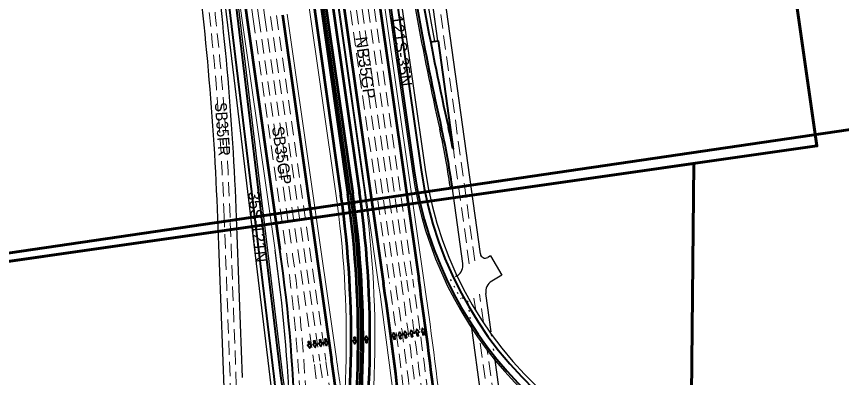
# Model space of a CAD drawing. Extents: x 2329387 to 2347382, y 6951580 to 6987999.
# Drawn here: x 2331270 to 2332942, y 6965088 to 6965820 of the extents above; entities that cross this region are included whole.
import ezdxf

# ---------------------------------------------------------------- set-up
doc = ezdxf.new("R2010")
doc.units = 0
doc.header["$LTSCALE"] = 9.6
doc.linetypes.add('DOTTED', pattern=[1.5, 0.3, -1.2])
doc.linetypes.add('MEDIUM_DASHED', pattern=[4.5, 3, -1.5])
for name, color, linetype, lineweight in [('26', 7, 'Continuous', 53), ('27', 7, 'Continuous', 40), ('28', 7, 'Continuous', 25), ('31', 7, 'Continuous', 53), ('41', 7, 'Continuous', 35), ('50', 7, 'MEDIUM_DASHED', 13), ('62', 7, 'Continuous', 60)]:
    doc.layers.add(name, color=color, linetype=linetype, lineweight=lineweight)
doc.layers.add('40', color=7, linetype='Continuous')

msp = doc.modelspace()

# ---------------------------------------------------------------- linework, layer by layer
at = {"layer": '26', "lineweight": 13}
for p, q in [((2331870.105, 6966212.955), (2332003.684, 6965277.65)), ((2331962.309, 6966218.061), (2332094.76, 6965290.657)), ((2331727.386, 6965811.815), (2331793.872, 6965346.29)), ((2331818.462, 6965824.822), (2331918.246, 6965126.152))]:
    msp.add_line(p, q, dxfattribs=at)
at = {"layer": '26'}
for p, q in [((2331880.005, 6966214.369), (2332013.584, 6965279.064)), ((2331967.521, 6966110.841), (2332084.861, 6965289.244)), ((2331737.286, 6965813.228), (2331803.772, 6965347.704)), ((2331808.563, 6965823.408), (2331908.346, 6965124.738))]:
    msp.add_line(p, q, dxfattribs=at)
at = {"layer": '26', "lineweight": 13}
for centre, radius, start, end in [((2343152.609, 6967443.552), 11541.156, 185.00662, 188.12795), ((2320619.05, 6963651.709), 11500.156, 4.81964, 8.12796), ((2320619.05, 6963651.709), 11592.156, 5.11219, 8.12796), ((2321018.843, 6963569.511), 11010, 7.56884, 8.12795)]:
    msp.add_arc(centre, radius, start, end, dxfattribs=at)
at = {"layer": '26'}
for centre, radius, start, end in [((2343152.609, 6967443.552), 11531.156, 185.00662, 188.12795), ((2320619.05, 6963651.709), 11510.156, 4.85569, 8.12795), ((2320619.05, 6963651.709), 11582.156, 5.08436, 8.12795), ((2321018.843, 6963569.511), 11000, 7.32798, 8.12796)]:
    msp.add_arc(centre, radius, start, end, dxfattribs=at)
at = {"layer": '27', "lineweight": 25}
for p, q in [((2331589.775, 6966698.599), (2331783.084, 6965089.223)), ((2331615.589, 6966701.7), (2331808.898, 6965092.328)), ((2331985.027, 6966115.578), (2332072.021, 6965506.454)), ((2332010.766, 6966119.254), (2332097.771, 6965510.058)), ((2332148.557, 6965475.47), (2332152.52, 6965476.018))]:
    msp.add_line(p, q, dxfattribs=at)
at = {"layer": '27'}
for p, q in [((2331597.718, 6966699.553), (2331791.027, 6965090.177)), ((2331611.618, 6966701.223), (2331804.926, 6965091.851)), ((2331988.987, 6966116.144), (2332075.967, 6965507.123)), ((2332002.846, 6966118.123), (2332089.804, 6965509.258)), ((2332109.02, 6965768.615), (2332124.869, 6965770.807)), ((2332155.26, 6965551.089), (2332124.869, 6965770.807))]:
    msp.add_line(p, q, dxfattribs=at)
for centre, radius, start, end in [((2339406.145, 6959556.474), 7976, 170.51466, 170.51466), ((2337735.465, 6966850.824), 5743.578, 187.87499, 192.65581), ((2337735.465, 6966850.824), 5729.578, 187.87499, 192.65581), ((2330747.502, 6965281.681), 1432.394, 10.9031, 12.65581), ((2330747.502, 6965281.681), 1418.394, 7.87499, 12.65581), ((2332846.073, 6965617.268), 777.944, 188.13957, 264.37892), ((2332846.073, 6965617.268), 763.944, 188.12796, 275.26524), ((2328562.616, 6964884.806), 3274.044, 1.33178, 8.12795), ((2332620.068, 6965189.757), 835, 186.84922, 291.74312), ((2332620.068, 6965189.757), 821, 186.84892, 289.1959)]:
    msp.add_arc(centre, radius, start, end, dxfattribs=at)
at = {"layer": '27', "lineweight": 25}
for centre, radius, start, end in [((2337735.465, 6966850.824), 5747.578, 187.87499, 192.65581), ((2337735.465, 6966850.824), 5721.578, 187.87499, 190.89172), ((2330747.502, 6965281.681), 1414.394, 7.87499, 12.65581), ((2332846.073, 6965617.268), 781.944, 188.14712, 258.99081), ((2332846.073, 6965617.268), 755.944, 188.15335, 275.26524), ((2328562.616, 6964884.806), 3264.044, 2.09116, 8.12795), ((2332620.068, 6965189.757), 843, 186.84922, 237.06532), ((2332620.068, 6965189.757), 817, 186.84892, 237.40672)]:
    msp.add_arc(centre, radius, start, end, dxfattribs=at)
at = {"layer": '28'}
for p, q in [((2332123.879, 6965770.67), (2331828.88, 6967903.45)), ((2332209.846, 6965338.909), (2332130.791, 6965910.461)), ((2332174.215, 6965319.168), (2332152.52, 6965476.018)), ((2331691.234, 6965045.796), (2331677.775, 6965411.534)), ((2331727.692, 6965088.403), (2331715.749, 6965412.931)), ((2332230.578, 6965335.045), (2332224.821, 6965331.659)), ((2332231.652, 6965181.258), (2332220.958, 6965258.571)), ((2332254.616, 6964737.881), (2332191.572, 6965193.676)), ((2332276.346, 6964858.124), (2332238.868, 6965129.083))]:
    msp.add_line(p, q, dxfattribs=at)
at = {"layer": '28', "linetype": 'DOTTED'}
for p, q in [((2332161.979, 6965294.109), (2332149.097, 6965286.649)), ((2332149.097, 6965286.649), (2332170.163, 6965248.102)), ((2332191.572, 6965193.676), (2332185.054, 6965240.803)), ((2332238.868, 6965129.083), (2332231.652, 6965181.258))]:
    msp.add_line(p, q, dxfattribs=at)
at = {"layer": '28'}
msp.add_lwpolyline([(2332230.638, 6965335.08), (2332253.716, 6965295.699), (2332233.05, 6965283.546)], dxfattribs=at)
for centre, radius, start, end in [((2325953.072, 6965200.86), 5766.578, 2.10758, 8.09153), ((2325953.072, 6965200.86), 5728.578, 2.10758, 8.09153), ((2332219.752, 6965340.279), 10, 187.87499, 300.45806), ((2332149.45, 6965315.743), 25, 305.35097, 7.87499), ((2332245.722, 6965261.996), 25, 120.45806, 187.87499)]:
    msp.add_arc(centre, radius, start, end, dxfattribs=at)
at = {"layer": '28', "linetype": 'DOTTED'}
for centre, radius, start, end in [((2332149.45, 6965315.743), 25, 300.0751, 305.35097), ((2332175.148, 6965239.433), 10, 7.87499, 119.89862)]:
    msp.add_arc(centre, radius, start, end, dxfattribs=at)
at = {"layer": '31'}
for p, q in [((2331690.26, 6967217.584), (2331941.267, 6965460.063)), ((2331700.159, 6967218.998), (2331951.166, 6965461.481)), ((2331714.019, 6967220.977), (2331965.025, 6965463.46)), ((2331676.4, 6967215.605), (2331927.407, 6965458.088))]:
    msp.add_line(p, q, dxfattribs=at)
at = {"layer": '31', "lineweight": 13}
for p, q in [((2331694.22, 6967218.149), (2331945.226, 6965460.633)), ((2331696.2, 6967218.432), (2331947.206, 6965460.916)), ((2331723.658, 6967224.211), (2331974.925, 6965464.874)), ((2331666.501, 6967214.191), (2331917.507, 6965456.674))]:
    msp.add_line(p, q, dxfattribs=at)
for radius, start in [(2082.483, 348.72065), (2084.483, 348.66216), (2112.483, 347.90133), (2054.483, 349.6074)]:
    msp.add_arc((2329883.662, 6965166.203), radius, start, 8.12795, dxfattribs=at)
at = {"layer": '31'}
for radius, start, end in [(2088.483, 348.54694, 8.12795), (2102.483, 348.16124, 8.12795), (2064.483, 349.27527, 8.12783), (2078.483, 348.83943, 8.12783)]:
    msp.add_arc((2329883.662, 6965166.203), radius, start, end, dxfattribs=at)
at = {"layer": '41'}
for points in [[(2332034.386, 6965165.369), (2332037.348, 6965165.851), (2332036.255, 6965172.57), (2332038.66, 6965172.961), (2332033.774, 6965179.461), (2332031.201, 6965171.747), (2332033.293, 6965172.088)], [(2332046.404, 6965166.587), (2332049.365, 6965167.069), (2332048.272, 6965173.787), (2332050.678, 6965174.179), (2332045.791, 6965180.678), (2332043.218, 6965172.965), (2332045.31, 6965173.305)], [(2332057.59, 6965168.3), (2332060.551, 6965168.782), (2332059.458, 6965175.501), (2332061.864, 6965175.892), (2332056.977, 6965182.392), (2332054.404, 6965174.678), (2332056.496, 6965175.019)], [(2332069.993, 6965170.363), (2332072.955, 6965170.845), (2332071.861, 6965177.563), (2332074.267, 6965177.954), (2332069.381, 6965184.454), (2332066.807, 6965176.74), (2332068.899, 6965177.081)], [(2332081.579, 6965172.35), (2332084.541, 6965172.832), (2332083.448, 6965179.551), (2332085.853, 6965179.942), (2332080.967, 6965186.442), (2332078.394, 6965178.728), (2332080.486, 6965179.069)], [(2332093.541, 6965174.409), (2332096.503, 6965174.891), (2332095.41, 6965181.609), (2332097.815, 6965182.001), (2332092.929, 6965188.5), (2332090.356, 6965180.787), (2332092.448, 6965181.127)], [(2331863.768, 6965161.668), (2331860.795, 6965161.255), (2331861.732, 6965154.513), (2331859.318, 6965154.178), (2331864.051, 6965147.566), (2331866.804, 6965155.218), (2331864.704, 6965154.926)], [(2331874.89, 6965163.288), (2331871.918, 6965162.875), (2331872.855, 6965156.133), (2331870.441, 6965155.798), (2331875.174, 6965149.186), (2331877.926, 6965156.838), (2331875.827, 6965156.546)], [(2331886.598, 6965165.261), (2331883.626, 6965164.848), (2331884.563, 6965158.106), (2331882.149, 6965157.77), (2331886.882, 6965151.159), (2331889.634, 6965158.81), (2331887.535, 6965158.519)], [(2331897.721, 6965166.88), (2331894.749, 6965166.468), (2331895.686, 6965159.726), (2331893.272, 6965159.39), (2331898.005, 6965152.778), (2331900.757, 6965160.43), (2331898.658, 6965160.138)], [(2331956.693, 6965170.066), (2331953.693, 6965170.008), (2331953.822, 6965163.203), (2331951.385, 6965163.156), (2331955.301, 6965156.03), (2331958.942, 6965163.3), (2331956.823, 6965163.26)], [(2331977.539, 6965158.705), (2331980.538, 6965158.807), (2331980.307, 6965165.61), (2331982.743, 6965165.692), (2331978.722, 6965172.76), (2331975.19, 6965165.436), (2331977.308, 6965165.508)]]:
    msp.add_lwpolyline(points, close=True, dxfattribs=at)
at = {"layer": '50'}
for p, q in [((2332198.633, 6965325.094), (2331727.576, 6968730.735)), ((2331891.884, 6966216.065), (2332025.463, 6965280.76)), ((2331903.764, 6966217.762), (2332037.343, 6965282.457)), ((2331915.643, 6966219.458), (2332049.222, 6965284.154)), ((2331927.523, 6966221.155), (2332061.102, 6965285.85)), ((2331939.402, 6966222.852), (2332072.981, 6965287.547)), ((2331749.165, 6965814.925), (2331815.651, 6965349.4)), ((2331761.045, 6965816.622), (2331827.531, 6965351.097)), ((2331772.924, 6965818.318), (2331872.708, 6965119.648)), ((2331784.804, 6965820.015), (2331884.587, 6965121.345)), ((2331796.683, 6965821.712), (2331896.467, 6965123.041)), ((2332187.381, 6965318.858), (2332155.26, 6965551.089)), ((2331732.763, 6964270.811), (2331690.766, 6965412.012)), ((2331743.91, 6964294.206), (2331702.758, 6965412.453)), ((2332200.508, 6965223.953), (2332196.973, 6965249.512)), ((2332215.991, 6965199.599), (2332207.989, 6965257.455)), ((2332266.878, 6964744.113), (2332208.776, 6965164.181)), ((2332278.224, 6964749.668), (2332223.696, 6965143.895))]:
    msp.add_line(p, q, dxfattribs=at)
for centre, radius, start, end in [((2343152.609, 6967443.552), 11519.156, 185.00662, 188.12795), ((2343152.609, 6967443.552), 11507.156, 185.00662, 188.12795), ((2343152.609, 6967443.552), 11495.156, 185.00662, 188.12795), ((2325953.072, 6965200.86), 5741.578, 2.10758, 8.09153), ((2325953.072, 6965200.86), 5753.578, 2.10758, 8.09153), ((2328562.616, 6964884.806), 3286.044, 0.68489, 8.12795), ((2328562.616, 6964884.806), 3298.044, 0.68489, 8.12795), ((2320619.05, 6963651.709), 11522.156, 4.89749, 8.12796), ((2320619.05, 6963651.709), 11534.156, 4.93774, 8.12796), ((2320619.05, 6963651.709), 11546.156, 4.98633, 8.12796), ((2320619.05, 6963651.709), 11558.156, 5.01384, 8.12796), ((2320619.05, 6963651.709), 11570.156, 5.04977, 8.12796), ((2321018.843, 6963569.511), 10964, 6.59599, 8.12796), ((2321018.843, 6963569.511), 10976, 6.82149, 8.12796), ((2321018.843, 6963569.511), 10988, 7.06405, 8.12796)]:
    msp.add_arc(centre, radius, start, end, dxfattribs=at)
at = {"layer": '62'}
for points in [[(2329936.564, 6972812.843), (2331011.084, 6965289.186), (2332891.999, 6965557.816), (2331817.479, 6973081.473)], [(2338114.665, 6964428.225), (2329704.893, 6963193.017), (2329428.787, 6965072.851), (2337838.559, 6966308.058)], [(2332642.295, 6965522.154), (2332560.849, 6957416.973), (2330660.943, 6957436.065), (2330739.467, 6965250.394)]]:
    msp.add_lwpolyline(points, close=True, dxfattribs=at)

# ---------------------------------------------------------------- texts
at = {"layer": '40'}
for s, rotation, p in [('121S-35N', 277.591, (2332028.744, 6965820.363)), ('NB35GP', 277.862, (2331956.309, 6965777.426)), ('35S-121N', 276.086, (2331739.238, 6965464.173))]:
    msp.add_text(s, height=24, rotation=rotation, dxfattribs=at).set_placement(p)
for s, rotation, width, p in [('SB35FR', 274.152, 0.9, (2331671.571, 6965645.412)), ('SB35GP', 277.862, 0.95, (2331787.457, 6965595.762))]:
    msp.add_text(s, height=24, rotation=rotation, dxfattribs=dict(at, width=width)).set_placement(p)

doc.saveas('drawing.dxf')
